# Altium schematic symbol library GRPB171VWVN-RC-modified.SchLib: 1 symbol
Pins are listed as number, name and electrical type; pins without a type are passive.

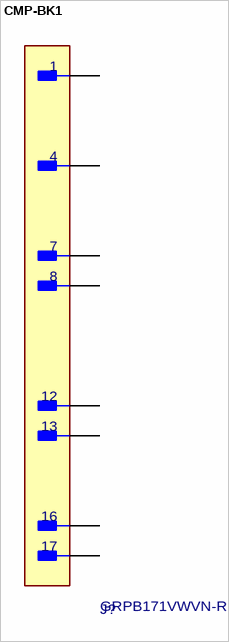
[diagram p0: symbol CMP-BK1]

## CMP-BK1
designator J?, comment GRPB171VWVN-RC
Connector Header Through Hole 17 position 0.050" (1.27mm); Manufacturer: Sullins Connector Solutions; Conn Gender: Male; SizeZ_mm: 4.4mm; ContactFinish: Gold; Current_A: 1A; Row_Count: 1; Conn Orientation: Straight; AEC Qualified: No
footprint FP-GRPB171VWVN-RC_HDR17-MFG
pins: 1, 4, 7, 8, 12, 13, 16, 17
